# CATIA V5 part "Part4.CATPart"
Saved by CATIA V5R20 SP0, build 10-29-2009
Part number: Part4
Bounding box of the stored display mesh (mm): x 0 to 10, y -14.996 to 14.996, z -14.99 to 174.99
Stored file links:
  E:\Ehsan\Catia\Tamrin\Digital Mockup\1\Part4.CATPart
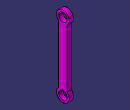
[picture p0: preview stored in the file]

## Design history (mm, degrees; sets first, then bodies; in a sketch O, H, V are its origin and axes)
Body1 (main body)
  Sketch1 on yz-plane, origin (0, 0, 0), H (0, 1, 0), V (0, 0, 1)
    arc A1 centre (0, 0) radius 15 from (-10, 11.1803) to (10, 11.1803) ccw
    circle A2 centre (0, 0) radius 10
    arc A3 centre (0, 160) radius 15 from (10, 148.8197) to (-10, 148.8197) ccw
    circle A4 centre (0, 160) radius 10
    line L1 (10, 148.8197) -> (10, 11.1803)
    point P2 (10, 148.8197)
    point P3 (10, 11.1803)
    point P4 (-10, 11.1803)
    point P5 (-10, 148.8197)
    line L2 (-10, 148.8197) -> (-10, 11.1803)
    radius A1 = 15
    radius A2 = 10
    distance P2 V = 10
    tangency: L1 A2
    symmetry: P3 P4 V, P2 P5 V, L1 L2 V
  Pad1: profile Sketch1, direction (1, 0, 0), length 10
